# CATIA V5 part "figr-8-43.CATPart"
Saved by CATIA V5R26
Part number: Part1
Bounding box of the stored display mesh (mm): x -50 to 50, y -50 to 50, z 0 to 25
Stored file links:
  D:\_Deepak\CATIA\CATIA V5-6R2016_Deepak\Resources\Part files\Partfiles\c08_catia_v5_6r2016_prt\figr-8-43.CATPart
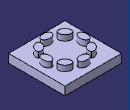
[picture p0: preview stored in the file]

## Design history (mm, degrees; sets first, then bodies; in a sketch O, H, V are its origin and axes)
Body1 (main body)
  Sketch1 on xy-plane, origin (0, 0, 0), H (1, 0, 0), V (0, 1, 0)
    line L1 (-50, 50) -> (50, 50)
    line L2 (50, 50) -> (50, -50)
    line L3 (50, -50) -> (-50, -50)
    line L4 (-50, -50) -> (-50, 50)
    axis line L5 (50, -50) -> (-50, 50)
    length L2 = 100
    length L3 = 100
    horizontal: L1 H, L3 H
    vertical: L2 V, L4 V
    midpoint: L5 O
  Pad1: profile Sketch1, direction (0, 0, 1), length 15
  Sketch2 on face of Pad1, origin (0, 0, 15), H (1, 0, 0), V (0, 1, 0)
    point P1 (0, -32.9864)
    ellipse A1 centre (0, -32.9864) semi-axes 9.9006, 6.5465 rotation 0
    point P2 (0, -26.4399)
    coincidence: P1 V, P2 V, A1 P2
  Pad2: profile Sketch2, direction (0, 0, 1), length 10
  CircPattern1: of Pad2, instances 8, angular step 45 {= 360.0*1 deg/CircPattern1.AngularNumber}, axis from edge of Sketch3
  Sketch3 on yz-plane, origin (0, 0, 0), H (0, 1, 0), V (0, 0, 1)
    line L1 (0, 0) -> (0, 18.4864)
    vertical: L1 V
